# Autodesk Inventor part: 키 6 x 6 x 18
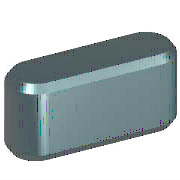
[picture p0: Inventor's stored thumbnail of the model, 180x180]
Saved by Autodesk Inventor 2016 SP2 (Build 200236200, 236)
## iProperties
IsCustomPart: 1
Created: 2012-02
Part Number: 키 6 x 6 x 18
Material: 강철, 연강
Description: 키 및 해당 키홈
Document SubType Name: Modeling
Standard: KS B 1311
Designer: mduedu
Standards Organization: KS
Language: ko-KR
Size Designation: 6 x 6 x 18
Categories: <MemberInstance><Categories><Category DisplayName="샤프트 부품" InternalName="7f7aeb1f-a693-4053-b835-cee3144e0d98" Mnemonic="SHFT"><Category DisplayName="키" Interna
Density: 1 g/cm^3
Appearance: 노란색
Author: mduedu
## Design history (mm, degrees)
workplane "Work Plane1"
workplane "Work Plane2"
sketch "스케치1"
  geometry: L1 (3, 3)-(15, 3); L2 (15, -3)-(3, -3); L3 (0, 9.4)-(0, -7.4) reference; L4 (-5, 0)-(30, 0) reference; L5 (18, 0)-(18, 7); A1 r 3 centre (3, 0) between (3, 3) and (3, -3); A2 r 3 centre (15, 0) between (15, -3) and (15, 3)
  constraints: 6 end point, 5 point on circle, 4 tangent, 3 point on line, 2 centre point, 1 horizontal, 1 parallel, 1 perpendicular
  dimensions: "d0" = 3 radius of A1 (= 0.5 x PB); "d13" = 3 radius of A2 (= 0.5 x PB); "d14" = 18 distance between parallel lines of L5 L3 (= NLG)
extrude "본체1" new body sketch "스케치1" taper "d3" = 0 deg; stored distance "d4" = 10
workplane "Work Plane3"
body "Solid1"
chamfer "모따기1" distance "d8" = 0.4 (= PHH); stored, may be unused: second distance "d9" = 0.4 (= PHH), angle "d15" = 45 deg
other parameters: "d1" = -3.5 (= -PNT), "d2" = 2.5 (= PH - PNT), "NLG" = 18 [user parameter; used in 3 equation terms], "PB" = 6 [user parameter; used in 2 equation terms], "PNT" = 3.5 [user parameter; used in 2 equation terms], "PH" = 6 [user parameter; used in 1 equation term], "PHH" = 0.4 [user parameter; used in 2 equation terms], "d10" = 0, "d16" = 0, "d17" = 0, "d18" = 0, "WDMIN" = 17 [user parameter], "PLB2" = 18 (= NLG) [user parameter], "WDMAX" = 22 [user parameter], "PLB1" = 18 (= NLG) [user parameter], "RR" = 0.16 [user parameter], "PUEB" = 2.8 [user parameter]
